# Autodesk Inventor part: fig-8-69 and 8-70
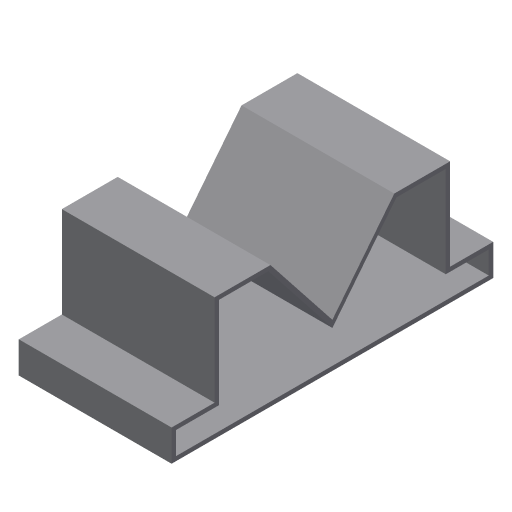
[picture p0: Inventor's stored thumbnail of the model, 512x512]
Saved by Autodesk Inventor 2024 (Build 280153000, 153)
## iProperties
Shininess: 77.0
Length Units: 11269
Angle Units: 11279
Time Units: 11290
Mass Units: 11283
Length Display Precision: 3
Angle Display Precision: 2
Created: 2002-01
Part Number: fig-8-69 and 8-70
Document SubType Name: Modeling
Designer: ***
Density: 1 g/cm^3
Material: Generic
Appearance: Default
Density: 0.0
Volumn: 0.0
Area: 0.0
PropertySet Name: Model Information
Control State: 0
Master: False
Checked Out: False
Author: ***
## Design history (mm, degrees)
sketch "Sketch2"
  geometry: L1 (0, 0)-(-14.184, 17.961); L2 (-14.184, 17.961)-(-26.987, 17.961); L3 (-26.987, 17.961)-(-26.987, -2.947); L4 (-26.987, -2.947)-(-36.842, -2.947); L5 (-36.842, -2.947)-(-36.842, -10.132); L6 (26.987, 17.961)-(26.987, -2.947); L7 (14.184, 17.961)-(26.987, 17.961); L8 (26.987, -2.947)-(36.842, -2.947); L9 (36.842, -10.132)-(-36.842, -10.132); L10 (36.842, -2.947)-(36.842, -10.132); L11 (0, 0)-(14.184, 17.961)
  constraints: 22 end point, 2 horizontal, 2 parallel, 1 perpendicular
extrude "Extrusion1" new body sketch "Sketch2" distance "d0" = 35; taper "d1" = 0 deg
shell "Shell3" dims "d13" = 1
body "Solid1"
node "Sketch1"
